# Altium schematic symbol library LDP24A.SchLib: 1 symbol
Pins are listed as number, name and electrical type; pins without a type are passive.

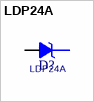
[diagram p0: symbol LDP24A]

## LDP24A
designator D?
footprint ST_R6
pins: 1 K, 2 A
